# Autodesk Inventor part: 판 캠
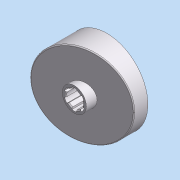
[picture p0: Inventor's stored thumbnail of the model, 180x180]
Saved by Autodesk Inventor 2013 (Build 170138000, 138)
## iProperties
Company: 한국ATC센터
Created: 2014-07
Part Number: 판 캠
Document SubType Name: 모델링
Designer: KYOUNG IL JANG
Material: 일반
Mass: 86.8262 g
Surface Area: 331.301 cm^2
Volume: 86.8262 cm^3
Density: 1 g/cm^3
변환 표준: STEP AP214IS
파일 이름: C:\Users\SeoGD\Desktop\?쒗뿕\??stp
전처리기: Build: 253, Release: 2010 SP1 - Date: Wed 07/29/2009
전송 단위: 밀리미터
불확실성: 0.01
Author: KYOUNG IL JANG
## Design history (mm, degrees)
node "작업 평면4"
sketch "스케치1"
  geometry: C1 r 44.5 at (0, 0); 1 further point
  constraints: 1 centre point, 1 coincident
  dimensions: "d25" = 89 diameter of C1
extrude "돌출1" new body sketch "스케치1" distance "d1" = 40; taper "d2" = 0 deg
sketch "스케치2"
  geometry: L1 (-44.5, 15)-(44.5, 38.847); L2 (-44.5, 0)-(-44.5, 40) reference; L3 (-44.5, 40)-(44.5, 40) reference; L4 (44.5, 0)-(44.5, 40) reference; 1 further point
  constraints: 2 end point, 2 point on line
  dimensions: "d26" = 15 distance of L2.start L1.start; "d27" = 75 deg angle of L1 L2
extrude "돌출2" cut sketch "스케치2" stored distance "d5" = 40; taper "d6" = 0 deg
node "작업 평면1"
sketch "스케치3"
  geometry: C1 r 13 at (0, 0); 1 further point
  constraints: 1 centre point, 1 coincident
  dimensions: "d9" = 26 diameter of C1
extrude "돌출3" join sketch "스케치3" distance "d10" = 38; taper "d11" = 0 deg
hole "구멍1" diameter "d14" = 18; stored, may be unused: countersink angle "d18" = 90 deg, drill point angle "d20" = 118 deg; dims "d12" = 10, "d13" = 10, "d15" = 6, "d16" = 4, "d17" = 2, "d19" = 8
feature "쉘2" dims "d29" = 5
sketch "스케치6"
  geometry: C1 r 17.5 at (0, 0); C2 r 14 at (0, 0) reference; 1 further point
  constraints: 1 centre point, 1 coincident
  dimensions: "d28" = 35 diameter of C1
extrude "돌출4" join sketch "스케치6" stored distance "d30" = 38; taper "d31" = 0 deg
fillet "모깎기1" dims "d32" = 3
chamfer "모따기1" distance "d21" = 1; stored, may be unused: second distance "d22" = 2, angle "d23" = 45 deg
sketch "스케치7"
  geometry: L1 (-12.374, 12.374)-(-27.931, 27.931); A1 r 39.5 centre (0, 0) between (-27.931, 27.931) and (0, 39.5) reference; 2 further points
  constraints: 2 end point, 2 point on circle, 1 point on line, 1 vertical alignment, 2 other
  dimensions: "d33" = 45 deg dimension on point (0, 0) L1.start A1.end
feature "리브1" sketch "스케치7" dims "d34" = 5, "d35" = 1, "d36" = 0
fillet "모깎기2" dims "d37" = 3
sketch "스케치8"
  geometry: L1 (2.5, 10.712)-(2.5, 8.646); L2 (-2.5, 10.712)-(-2.5, 8.646); A1 r 11 centre (0, 0) between (2.5, 10.712) and (-2.5, 10.712); A2 r 9 centre (0, 0) between (2.5, 8.646) and (-2.5, 8.646) reference; 1 further point
  constraints: 4 end point, 4 point on circle, 2 parallel, 1 centre point, 1 coincident, 1 vertical
  dimensions: "d41" = 22 diameter of A1; "d42" = 5 distance between parallel lines of L1 L2
extrude "돌출5" cut sketch "스케치8" stored distance "d43" = 38; taper "d44" = 0 deg
fillet "모깎기3" dims "d48" = 1
node "솔리드1"
node "솔리드 본체"
node "곡면 본체"
pattern_circular "원형 패턴1" dims angle "d39" = 360 deg
pattern_circular "원형 패턴2" dims angle "d46" = 360 deg
node "솔리드2"
